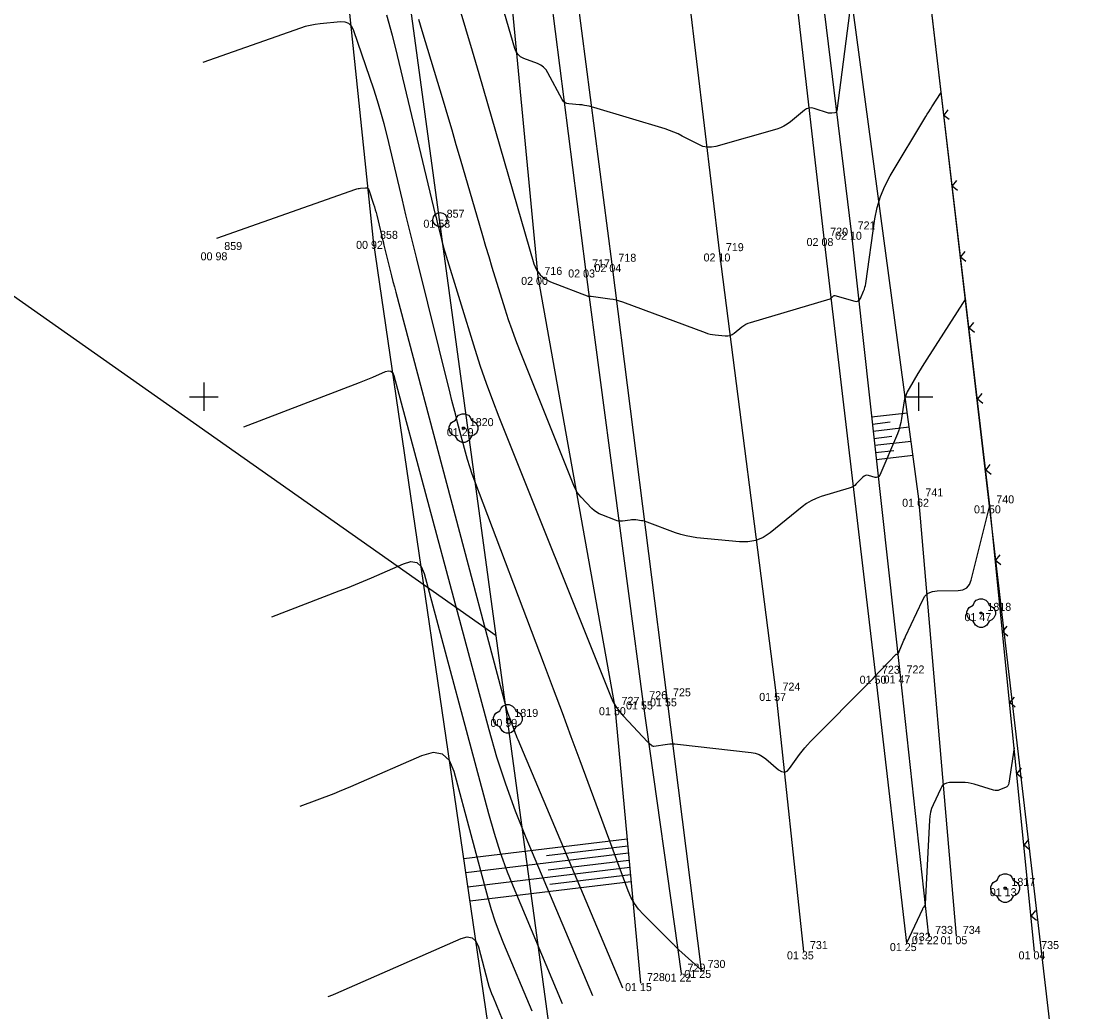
# Model space of a CAD drawing. Extents: x -711234 to -710007, y -1026313 to -1025448.
# Drawn here: x -710906.39 to -710869.22, y -1026121.51 to -1026086.87 of the extents above; entities that cross this region are included whole.
import ezdxf

# ---------------------------------------------------------------- set-up
doc = ezdxf.new("R2010")
doc.units = 0
for name, color, linetype in [('Ex_Major Contours', 7, 'Continuous'), ('Ex_Minor Contours', 7, 'Continuous'), ('Z_body', 7, 'Continuous'), ('Z_body_cisla', 7, 'Continuous'), ('Z_body_vysky_redukovane', 7, 'Continuous'), ('Z_hektometricka_sit', 7, 'Continuous'), ('Z_hrany_paty', 7, 'Continuous'), ('Z_katastr_hranice', 7, 'Continuous'), ('Z_komunikace', 7, 'Continuous'), ('Z_komunikace_osa', 7, 'Continuous'), ('Z_ploty', 7, 'Continuous'), ('Z_ploty_znacky', 7, 'Continuous'), ('Z_pole_rozhranni', 7, 'Continuous'), ('Z_technicke_srafy', 7, 'Continuous'), ('Z_vdz12_plna', 7, 'Continuous'), ('Z_zelen_jednotliva', 7, 'Continuous')]:
    doc.layers.add(name, color=color, linetype=linetype)

# ---------------------------------------------------------------- blocks, each defined once
blk = doc.blocks.new('POINT_DISPLAY')
blk.add_line((0, 0), (0, 0))
blk = doc.blocks.new('Z10001')
blk.add_circle((0, 0), 0.25)
blk = doc.blocks.new('Z24')
for p, q in [((-0.28, 0.28), (-0.23, 0.38)), ((-0.23, 0.38), (-0.17, 0.45)), ((-0.17, 0.45), (-0.05, 0.5)), ((-0.05, 0.5), (0.05, 0.5)), ((0.05, 0.5), (0.17, 0.45)), ((0.17, 0.45), (0.23, 0.38)), ((0.23, 0.38), (0.28, 0.28)), ((-0.5, 0.05), (-0.47, 0.13)), ((-0.5, -0.05), (-0.5, 0.05)), ((-0.47, 0.13), (-0.42, 0.2)), ((-0.42, 0.2), (-0.28, 0.28)), ((-0.03, -0.03), (-0.03, 0.03)), ((-0.03, 0.03), (0.03, 0.03)), ((0.03, 0.03), (0.03, -0.03)), ((0.28, 0.28), (0.42, 0.2)), ((0.42, 0.2), (0.47, 0.13)), ((0.47, 0.13), (0.5, 0.05)), ((0.5, 0.05), (0.5, -0.05)), ((-0.45, -0.17), (-0.5, -0.05)), ((-0.38, -0.23), (-0.45, -0.17)), ((-0.28, -0.28), (-0.38, -0.23)), ((-0.2, -0.42), (-0.28, -0.28)), ((0.03, -0.03), (-0.03, -0.03)), ((0.28, -0.28), (0.2, -0.42)), ((0.38, -0.23), (0.28, -0.28)), ((0.45, -0.17), (0.38, -0.23)), ((0.5, -0.05), (0.45, -0.17)), ((-0.13, -0.47), (-0.2, -0.42)), ((-0.05, -0.5), (-0.13, -0.47)), ((0.05, -0.5), (-0.05, -0.5)), ((0.13, -0.47), (0.05, -0.5)), ((0.2, -0.42), (0.13, -0.47))]:
    blk.add_line(p, q)
blk = doc.blocks.new('Z212')
for p, q in [((-0.17, 0.17), (0, 0)), ((0, 0), (0.17, 0.17))]:
    blk.add_line(p, q)

msp = doc.modelspace()

# ---------------------------------------------------------------- linework, layer by layer
at = {"layer": 'Ex_Major Contours'}
for points in [[(-710891.08, -1026086.336), (-710890.846, -1026087.122), (-710890.615, -1026087.909), (-710890.385, -1026088.696), (-710888.454, -1026095.349), (-710888.367, -1026095.561), (-710888.241, -1026095.737), (-710888.076, -1026095.877), (-710887.871, -1026095.981), (-710886.537, -1026096.49), (-710886.531, -1026096.492), (-710886.525, -1026096.493), (-710886.518, -1026096.493), (-710886.512, -1026096.493), (-710886.486, -1026096.489), (-710886.479, -1026096.489), (-710886.472, -1026096.488), (-710886.466, -1026096.489), (-710886.459, -1026096.489), (-710885.798, -1026096.572), (-710885.686, -1026096.589), (-710885.576, -1026096.613), (-710885.468, -1026096.643), (-710885.361, -1026096.679), (-710882.463, -1026097.757), (-710882.379, -1026097.785), (-710882.294, -1026097.808), (-710882.207, -1026097.825), (-710882.119, -1026097.837), (-710881.761, -1026097.873), (-710881.677, -1026097.873), (-710881.598, -1026097.858), (-710881.523, -1026097.827), (-710881.454, -1026097.78), (-710881.185, -1026097.561), (-710881.115, -1026097.51), (-710881.042, -1026097.467), (-710880.965, -1026097.431), (-710880.884, -1026097.402), (-710878.095, -1026096.572), (-710878.078, -1026096.566), (-710878.063, -1026096.558), (-710878.048, -1026096.548), (-710878.035, -1026096.535), (-710877.985, -1026096.483), (-710877.972, -1026096.472), (-710877.957, -1026096.466), (-710877.942, -1026096.464), (-710877.925, -1026096.466), (-710877.223, -1026096.657), (-710877.16, -1026096.665), (-710877.107, -1026096.652), (-710877.064, -1026096.618), (-710877.032, -1026096.564), (-710876.921, -1026096.305), (-710876.896, -1026096.24), (-710876.875, -1026096.173), (-710876.859, -1026096.106), (-710876.846, -1026096.037), (-710876.524, -1026093.774), (-710876.448, -1026093.381), (-710876.335, -1026093.001), (-710876.183, -1026092.634), (-710875.994, -1026092.281), (-710874.745, -1026090.204), (-710874.693, -1026090.119), (-710874.64, -1026090.033), (-710874.587, -1026089.948), (-710874.533, -1026089.864), (-710874.208, -1026089.358)], [(-710899.55, -1026094.458), (-710894.69, -1026092.747), (-710894.649, -1026092.734), (-710894.607, -1026092.723), (-710894.565, -1026092.715), (-710894.522, -1026092.71), (-710894.35, -1026092.694), (-710894.311, -1026092.695), (-710894.278, -1026092.708), (-710894.254, -1026092.732), (-710894.236, -1026092.768), (-710894.068, -1026093.265), (-710894.036, -1026093.361), (-710894.007, -1026093.459), (-710893.98, -1026093.557), (-710893.955, -1026093.656), (-710893.824, -1026094.204), (-710893.794, -1026094.328), (-710893.764, -1026094.453), (-710893.733, -1026094.577), (-710893.703, -1026094.701), (-710893.483, -1026095.588), (-710893.435, -1026095.777), (-710893.387, -1026095.966), (-710893.339, -1026096.155), (-710893.289, -1026096.343), (-710889.444, -1026110.845), (-710889.432, -1026110.888), (-710889.42, -1026110.93), (-710889.405, -1026110.972), (-710889.39, -1026111.014), (-710889.328, -1026111.179), (-710889.312, -1026111.221), (-710889.297, -1026111.262), (-710889.281, -1026111.303), (-710889.266, -1026111.345), (-710889.134, -1026111.701), (-710889.107, -1026111.774), (-710889.078, -1026111.847), (-710889.049, -1026111.919), (-710889.019, -1026111.991), (-710885.361, -1026120.674)], [(-710895.657, -1026120.978), (-710895.495, -1026120.915), (-710895.468, -1026120.905), (-710895.441, -1026120.894), (-710895.414, -1026120.883), (-710895.387, -1026120.871), (-710891.007, -1026118.953), (-710890.791, -1026118.893), (-710890.617, -1026118.922), (-710890.486, -1026119.039), (-710890.397, -1026119.246), (-710890.066, -1026120.484), (-710890.028, -1026120.617), (-710889.985, -1026120.748), (-710889.938, -1026120.877), (-710889.887, -1026121.005), (-710889.565, -1026121.769)]]:
    msp.add_lwpolyline(points, dxfattribs=at)
at = {"layer": 'Ex_Minor Contours'}
for points in [[(-710877.365, -1026086.208), (-710877.862, -1026090), (-710877.869, -1026090.025), (-710877.882, -1026090.044), (-710877.9, -1026090.058), (-710877.925, -1026090.066), (-710878.036, -1026090.085), (-710878.064, -1026090.088), (-710878.091, -1026090.088), (-710878.119, -1026090.084), (-710878.146, -1026090.078), (-710878.655, -1026089.917), (-710878.747, -1026089.898), (-710878.834, -1026089.903), (-710878.916, -1026089.931), (-710878.994, -1026089.983), (-710879.482, -1026090.386), (-710879.591, -1026090.468), (-710879.708, -1026090.537), (-710879.831, -1026090.594), (-710879.96, -1026090.638), (-710882.088, -1026091.247), (-710882.243, -1026091.276), (-710882.395, -1026091.276), (-710882.543, -1026091.245), (-710882.689, -1026091.185), (-710883.265, -1026090.882), (-710883.41, -1026090.809), (-710883.559, -1026090.744), (-710883.71, -1026090.686), (-710883.864, -1026090.636), (-710886.362, -1026089.88), (-710886.403, -1026089.868), (-710886.443, -1026089.858), (-710886.484, -1026089.848), (-710886.525, -1026089.84), (-710886.69, -1026089.81), (-710886.732, -1026089.803), (-710886.773, -1026089.797), (-710886.815, -1026089.792), (-710886.857, -1026089.789), (-710887.238, -1026089.759), (-710887.31, -1026089.745), (-710887.372, -1026089.716), (-710887.424, -1026089.671), (-710887.466, -1026089.61), (-710887.965, -1026088.671), (-710888.033, -1026088.566), (-710888.117, -1026088.477), (-710888.215, -1026088.405), (-710888.329, -1026088.351), (-710888.813, -1026088.166), (-710888.924, -1026088.111), (-710889.013, -1026088.035), (-710889.081, -1026087.94), (-710889.128, -1026087.826), (-710890.128, -1026084.381)], [(-710882.61, -1026120.05), (-710883.389, -1026119.345), (-710883.406, -1026119.33), (-710883.422, -1026119.314), (-710883.438, -1026119.298), (-710883.454, -1026119.281), (-710883.517, -1026119.215), (-710883.533, -1026119.198), (-710883.549, -1026119.182), (-710883.565, -1026119.165), (-710883.581, -1026119.149), (-710884.625, -1026118.11), (-710884.793, -1026117.924), (-710884.938, -1026117.723), (-710885.061, -1026117.508), (-710885.16, -1026117.278), (-710886.84, -1026112.734), (-710887.15, -1026111.898), (-710887.461, -1026111.062), (-710887.775, -1026110.227), (-710888.089, -1026109.393), (-710890.524, -1026102.955), (-710890.616, -1026102.705), (-710890.7, -1026102.452), (-710890.778, -1026102.197), (-710890.85, -1026101.94), (-710891.124, -1026100.908), (-710891.192, -1026100.65), (-710891.258, -1026100.391), (-710891.324, -1026100.133), (-710891.389, -1026099.874), (-710892.555, -1026095.174), (-710892.682, -1026094.662), (-710892.807, -1026094.149), (-710892.932, -1026093.636), (-710893.055, -1026093.123), (-710893.595, -1026090.861), (-710893.697, -1026090.453), (-710893.809, -1026090.049), (-710893.93, -1026089.647), (-710894.06, -1026089.248), (-710894.755, -1026087.199), (-710894.827, -1026087.053), (-710894.93, -1026086.953), (-710895.062, -1026086.9), (-710895.225, -1026086.893), (-710895.936, -1026086.959), (-710896.113, -1026086.981), (-710896.287, -1026087.014), (-710896.459, -1026087.057), (-710896.628, -1026087.111), (-710900.045, -1026088.315)], [(-710893.611, -1026086.639), (-710893.415, -1026087.35), (-710893.235, -1026088.066), (-710891.907, -1026093.627), (-710891.881, -1026093.737), (-710891.854, -1026093.846), (-710891.827, -1026093.956), (-710891.8, -1026094.065), (-710891.692, -1026094.503), (-710891.664, -1026094.612), (-710891.634, -1026094.72), (-710891.603, -1026094.829), (-710891.571, -1026094.937), (-710890.523, -1026098.332), (-710890.331, -1026098.931), (-710890.127, -1026099.527), (-710889.911, -1026100.118), (-710889.683, -1026100.705), (-710885.779, -1026110.463), (-710885.691, -1026110.656), (-710885.586, -1026110.838), (-710885.465, -1026111.01), (-710885.326, -1026111.171), (-710884.477, -1026112.069), (-710884.461, -1026112.086), (-710884.445, -1026112.102), (-710884.428, -1026112.118), (-710884.412, -1026112.133), (-710884.344, -1026112.194), (-710884.326, -1026112.207), (-710884.307, -1026112.216), (-710884.287, -1026112.22), (-710884.265, -1026112.219), (-710883.785, -1026112.156), (-710883.697, -1026112.147), (-710883.61, -1026112.144), (-710883.522, -1026112.146), (-710883.435, -1026112.153), (-710880.852, -1026112.447), (-710880.712, -1026112.473), (-710880.58, -1026112.519), (-710880.457, -1026112.584), (-710880.343, -1026112.669), (-710879.902, -1026113.047), (-710879.795, -1026113.115), (-710879.694, -1026113.13), (-710879.6, -1026113.092), (-710879.512, -1026113), (-710879.163, -1026112.515), (-710879.074, -1026112.396), (-710878.981, -1026112.282), (-710878.884, -1026112.171), (-710878.782, -1026112.064), (-710876.686, -1026109.947), (-710876.593, -1026109.853), (-710876.501, -1026109.759), (-710876.409, -1026109.664), (-710876.318, -1026109.569), (-710875.78, -1026109.007), (-710875.776, -1026109.003), (-710875.77, -1026109.001), (-710875.765, -1026109), (-710875.759, -1026109.001), (-710875.734, -1026109.008), (-710875.729, -1026109.008), (-710875.724, -1026109.007), (-710875.72, -1026109.004), (-710875.717, -1026108.999), (-710875.563, -1026108.638), (-710875.536, -1026108.576), (-710875.509, -1026108.514), (-710875.481, -1026108.453), (-710875.453, -1026108.391), (-710874.866, -1026107.124), (-710874.776, -1026106.978), (-710874.659, -1026106.873), (-710874.516, -1026106.809), (-710874.346, -1026106.786), (-710873.613, -1026106.775), (-710873.447, -1026106.751), (-710873.315, -1026106.682), (-710873.219, -1026106.57), (-710873.157, -1026106.414), (-710872.5, -1026103.8)], [(-710873.354, -1026096.579), (-710874.712, -1026098.692), (-710874.791, -1026098.816), (-710874.869, -1026098.94), (-710874.946, -1026099.065), (-710875.022, -1026099.19), (-710875.333, -1026099.708), (-710875.398, -1026099.829), (-710875.45, -1026099.954), (-710875.489, -1026100.084), (-710875.515, -1026100.219), (-710875.593, -1026100.767), (-710875.617, -1026100.902), (-710875.649, -1026101.036), (-710875.69, -1026101.166), (-710875.74, -1026101.295), (-710876.358, -1026102.742), (-710876.385, -1026102.788), (-710876.422, -1026102.817), (-710876.466, -1026102.828), (-710876.52, -1026102.821), (-710876.75, -1026102.758), (-710876.806, -1026102.75), (-710876.857, -1026102.756), (-710876.905, -1026102.778), (-710876.948, -1026102.813), (-710877.177, -1026103.052), (-710877.231, -1026103.103), (-710877.29, -1026103.144), (-710877.355, -1026103.178), (-710877.424, -1026103.204), (-710878.401, -1026103.495), (-710878.584, -1026103.559), (-710878.757, -1026103.64), (-710878.922, -1026103.737), (-710879.077, -1026103.852), (-710880.188, -1026104.756), (-710880.432, -1026104.92), (-710880.692, -1026105.029), (-710880.97, -1026105.082), (-710881.263, -1026105.079), (-710882.751, -1026104.931), (-710882.943, -1026104.905), (-710883.132, -1026104.868), (-710883.318, -1026104.818), (-710883.501, -1026104.756), (-710884.499, -1026104.385), (-710884.547, -1026104.369), (-710884.595, -1026104.356), (-710884.644, -1026104.345), (-710884.694, -1026104.338), (-710884.893, -1026104.312), (-710884.943, -1026104.308), (-710884.993, -1026104.306), (-710885.043, -1026104.308), (-710885.093, -1026104.313), (-710885.361, -1026104.348), (-710885.422, -1026104.352), (-710885.482, -1026104.349), (-710885.541, -1026104.338), (-710885.599, -1026104.32), (-710886.082, -1026104.136), (-710886.178, -1026104.093), (-710886.268, -1026104.04), (-710886.351, -1026103.978), (-710886.428, -1026103.905), (-710886.798, -1026103.516), (-710886.879, -1026103.422), (-710886.95, -1026103.322), (-710887.011, -1026103.216), (-710887.063, -1026103.103), (-710888.951, -1026098.384), (-710889.09, -1026098.027), (-710889.221, -1026097.667), (-710889.345, -1026097.306), (-710889.461, -1026096.941), (-710889.913, -1026095.478), (-710890.025, -1026095.112), (-710890.136, -1026094.745), (-710890.245, -1026094.378), (-710890.353, -1026094.011), (-710891.025, -1026091.696), (-710891.173, -1026091.187), (-710891.322, -1026090.68), (-710891.473, -1026090.172), (-710891.625, -1026089.665), (-710892.366, -1026087.198), (-710892.482, -1026086.804)], [(-710898.606, -1026101.059), (-710894.554, -1026099.507), (-710894.439, -1026099.462), (-710894.324, -1026099.415), (-710894.21, -1026099.368), (-710894.096, -1026099.319), (-710893.643, -1026099.12), (-710893.54, -1026099.091), (-710893.457, -1026099.105), (-710893.394, -1026099.161), (-710893.352, -1026099.26), (-710890.039, -1026111.635), (-710889.764, -1026112.596), (-710889.456, -1026113.546), (-710889.116, -1026114.485), (-710888.744, -1026115.413), (-710886.412, -1026120.948)], [(-710897.623, -1026107.698), (-710895.267, -1026106.796), (-710894.982, -1026106.685), (-710894.698, -1026106.57), (-710894.416, -1026106.453), (-710894.135, -1026106.331), (-710893.015, -1026105.841), (-710892.76, -1026105.77), (-710892.555, -1026105.804), (-710892.401, -1026105.943), (-710892.296, -1026106.186), (-710890.048, -1026114.584), (-710889.852, -1026115.269), (-710889.633, -1026115.947), (-710889.39, -1026116.616), (-710889.125, -1026117.277), (-710887.463, -1026121.221)], [(-710888.514, -1026121.495), (-710889.506, -1026119.141), (-710889.664, -1026118.747), (-710889.809, -1026118.347), (-710889.94, -1026117.943), (-710890.057, -1026117.534), (-710891.241, -1026113.112), (-710891.407, -1026112.724), (-710891.653, -1026112.503), (-710891.98, -1026112.449), (-710892.387, -1026112.561), (-710894.683, -1026113.567), (-710894.876, -1026113.65), (-710895.07, -1026113.731), (-710895.265, -1026113.81), (-710895.461, -1026113.886), (-710896.64, -1026114.338)], [(-710871.652, -1026112.278), (-710871.837, -1026113.512), (-710871.85, -1026113.563), (-710871.875, -1026113.606), (-710871.91, -1026113.64), (-710871.957, -1026113.666), (-710872.163, -1026113.752), (-710872.215, -1026113.768), (-710872.267, -1026113.776), (-710872.32, -1026113.774), (-710872.373, -1026113.762), (-710873.052, -1026113.553), (-710873.157, -1026113.525), (-710873.263, -1026113.506), (-710873.37, -1026113.495), (-710873.479, -1026113.492), (-710873.915, -1026113.498), (-710874.016, -1026113.512), (-710874.102, -1026113.55), (-710874.171, -1026113.613), (-710874.225, -1026113.7), (-710874.489, -1026114.271), (-710874.542, -1026114.401), (-710874.582, -1026114.534), (-710874.609, -1026114.67), (-710874.622, -1026114.809), (-710874.767, -1026117.74), (-710874.769, -1026117.757), (-710874.773, -1026117.774), (-710874.78, -1026117.79), (-710874.789, -1026117.805), (-710874.828, -1026117.864), (-710874.838, -1026117.879), (-710874.847, -1026117.895), (-710874.856, -1026117.91), (-710874.863, -1026117.926), (-710875.42, -1026119.11)]]:
    msp.add_lwpolyline(points, dxfattribs=at)
at = {"layer": 'Z_hektometricka_sit'}
for p, q in [((-710900, -1026099.5), (-710900, -1026100.5)), ((-710875, -1026099.5), (-710875, -1026100.5)), ((-710900.5, -1026100), (-710899.5, -1026100)), ((-710875.5, -1026100), (-710874.5, -1026100))]:
    msp.add_line(p, q, dxfattribs=at)
at = {"layer": 'Z_hrany_paty'}
for p, q in [((-710889.85, -1026079.72), (-710888.32, -1026095.81)), ((-710874.99, -1026103.57), (-710877.27, -1026086.56)), ((-710888.32, -1026095.81), (-710885.62, -1026110.86)), ((-710873.67, -1026118.87), (-710874.99, -1026103.57)), ((-710885.62, -1026110.86), (-710884.73, -1026120.51))]:
    msp.add_line(p, q, dxfattribs=at)
at = {"layer": 'Z_katastr_hranice'}
msp.add_line((-710885.22, -1026141.88), (-710889.78, -1026108.36), dxfattribs=at)
for points in [[(-710889.78, -1026108.36), (-711036.33, -1026005.25), (-711182.89, -1025902.14)], [(-710869.22, -1026132.07), (-710876.56, -1026069.18), (-710887.07, -1025978.66), (-710888.56, -1025976.86)], [(-710889.78, -1026108.36), (-710894.44, -1026074.09), (-710896.69, -1026055.45)]]:
    msp.add_lwpolyline(points, dxfattribs=at)
at = {"layer": 'Z_komunikace'}
for p, q in [((-710879.33, -1026078.09), (-710877.36, -1026094.23)), ((-710888.71, -1026079.46), (-710886.65, -1026095.55)), ((-710877.36, -1026094.23), (-710875.64, -1026109.75)), ((-710886.65, -1026095.55), (-710884.65, -1026110.66)), ((-710875.64, -1026109.75), (-710874.65, -1026118.87)), ((-710884.65, -1026110.66), (-710883.3, -1026120.18))]:
    msp.add_line(p, q, dxfattribs=at)
at = {"layer": 'Z_komunikace_osa'}
for p, q in [((-710883.93, -1026078.67), (-710881.96, -1026094.99)), ((-710881.96, -1026094.99), (-710879.99, -1026110.36)), ((-710879.99, -1026110.36), (-710879.02, -1026119.4))]:
    msp.add_line(p, q, dxfattribs=at)
at = {"layer": 'Z_ploty'}
for p, q in [((-710872.5, -1026103.8), (-710874.55, -1026086.47)), ((-710870.94, -1026119.4), (-710872.5, -1026103.8))]:
    msp.add_line(p, q, dxfattribs=at)
at = {"layer": 'Z_pole_rozhranni'}
for p, q in [((-710894.07, -1026094.55), (-710896.88, -1026067.52)), ((-710890.07, -1026121.9), (-710894.07, -1026094.55))]:
    msp.add_line(p, q, dxfattribs=at)
at = {"layer": 'Z_technicke_srafy'}
for p, q in [((-710876.64, -1026100.71), (-710875.39, -1026100.56)), ((-710876.61, -1026100.96), (-710875.99, -1026100.88)), ((-710876.59, -1026101.21), (-710875.33, -1026101.05)), ((-710876.56, -1026101.46), (-710875.93, -1026101.38)), ((-710876.53, -1026101.7), (-710875.26, -1026101.55)), ((-710876.5, -1026101.95), (-710875.87, -1026101.88)), ((-710876.48, -1026102.2), (-710875.19, -1026102.04)), ((-710885.19, -1026115.48), (-710890.91, -1026116.16)), ((-710885.15, -1026115.97), (-710890.84, -1026116.65)), ((-710885.17, -1026115.72), (-710888.02, -1026116.06)), ((-710885.13, -1026116.22), (-710887.96, -1026116.56)), ((-710885.1, -1026116.47), (-710890.77, -1026117.15)), ((-710885.06, -1026116.97), (-710890.69, -1026117.64)), ((-710885.08, -1026116.72), (-710887.9, -1026117.06))]:
    msp.add_line(p, q, dxfattribs=at)
at = {"layer": 'Z_vdz12_plna'}
for p, q in [((-710880.19, -1026078.24), (-710878.31, -1026094.45)), ((-710887.8, -1026079.37), (-710885.73, -1026095.36)), ((-710878.31, -1026094.45), (-710876.5, -1026109.76)), ((-710885.73, -1026095.36), (-710883.81, -1026110.55)), ((-710876.5, -1026109.76), (-710875.42, -1026119.11)), ((-710883.81, -1026110.55), (-710882.61, -1026120.05))]:
    msp.add_line(p, q, dxfattribs=at)

# ---------------------------------------------------------------- block references
at = {"layer": 'Z_body'}
for p in [(-710891.74, -1026093.81), (-710877.36, -1026094.23), (-710894.07, -1026094.55), (-710878.31, -1026094.45), (-710899.51, -1026094.95), (-710881.96, -1026094.99), (-710885.73, -1026095.36), (-710888.32, -1026095.81), (-710886.65, -1026095.55), (-710890.92, -1026101.1), (-710874.99, -1026103.57), (-710872.5, -1026103.8), (-710872.81, -1026107.57), (-710876.5, -1026109.76), (-710875.64, -1026109.75), (-710879.99, -1026110.36), (-710884.65, -1026110.66), (-710883.81, -1026110.55), (-710885.62, -1026110.86), (-710889.37, -1026111.27), (-710871.97, -1026117.19), (-710874.65, -1026118.87), (-710873.67, -1026118.87), (-710875.42, -1026119.11), (-710879.02, -1026119.4), (-710870.94, -1026119.4), (-710882.61, -1026120.05), (-710883.3, -1026120.18), (-710884.73, -1026120.51)]:
    msp.add_blockref('POINT_DISPLAY', p, dxfattribs=at)
at = {"layer": 'Z_ploty_znacky'}
for p, rotation in [((-710874.12, -1026090.15), -83.30000000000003), ((-710873.82, -1026092.63), -83.30000000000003), ((-710873.53, -1026095.11), -83.30000000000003), ((-710873.23, -1026097.59), -83.30000000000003), ((-710872.94, -1026100.08), -83.30000000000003), ((-710872.65, -1026102.56), -83.30000000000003), ((-710872.31, -1026105.72), -84.30000000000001), ((-710872.06, -1026108.21), -84.30000000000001), ((-710871.81, -1026110.69), -84.30000000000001), ((-710871.56, -1026113.18), -84.30000000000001), ((-710871.31, -1026115.67), -84.30000000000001), ((-710871.06, -1026118.16), -84.30000000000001)]:
    msp.add_blockref('Z212', p, dxfattribs=dict(at, rotation=rotation))
at = {"layer": 'Z_zelen_jednotliva'}
for name, p in [('Z10001', (-710891.74, -1026093.81)), ('Z24', (-710890.92, -1026101.1)), ('Z24', (-710872.81, -1026107.57)), ('Z24', (-710889.37, -1026111.27)), ('Z24', (-710871.97, -1026117.19))]:
    msp.add_blockref(name, p, dxfattribs=at)

# ---------------------------------------------------------------- texts
at = {"layer": 'Z_body_cisla'}
for s, p in [('857', (-710891.51, -1026093.74)), ('721', (-710877.13, -1026094.15)), ('858', (-710893.84, -1026094.48)), ('720', (-710878.09, -1026094.37)), ('859', (-710899.29, -1026094.87)), ('719', (-710881.74, -1026094.91)), ('718', (-710885.5, -1026095.28)), ('716', (-710888.09, -1026095.74)), ('717', (-710886.42, -1026095.48)), ('1820', (-710890.7, -1026101.03)), ('741', (-710874.76, -1026103.49)), ('740', (-710872.28, -1026103.73)), ('1818', (-710872.59, -1026107.49)), ('723', (-710876.28, -1026109.69)), ('722', (-710875.42, -1026109.68)), ('724', (-710879.76, -1026110.28)), ('726', (-710884.42, -1026110.58)), ('725', (-710883.59, -1026110.48)), ('727', (-710885.39, -1026110.78)), ('1819', (-710889.14, -1026111.2)), ('1817', (-710871.75, -1026117.11)), ('733', (-710874.42, -1026118.79)), ('734', (-710873.45, -1026118.79)), ('732', (-710875.2, -1026119.03)), ('731', (-710878.8, -1026119.32)), ('735', (-710870.71, -1026119.32)), ('729', (-710883.08, -1026120.11)), ('730', (-710882.38, -1026119.98)), ('728', (-710884.5, -1026120.44))]:
    msp.add_text(s, height=0.28, dxfattribs=at).set_placement(p)
at = {"layer": 'Z_body_vysky_redukovane'}
for s, p in [('01 53', (-710892.323, -1026094.09)), ('02 10', (-710877.92, -1026094.51)), ('00 92', (-710894.677, -1026094.83)), ('02 08', (-710878.917, -1026094.73)), ('00 98', (-710900.117, -1026095.23)), ('02 10', (-710882.52, -1026095.27)), ('02 04', (-710886.337, -1026095.64)), ('02 00', (-710888.903, -1026096.09)), ('02 03', (-710887.257, -1026095.83)), ('01 29', (-710891.503, -1026101.38)), ('01 62', (-710875.573, -1026103.85)), ('01 50', (-710873.06, -1026104.08)), ('01 47', (-710873.393, -1026107.85)), ('01 50', (-710877.06, -1026110.04)), ('01 47', (-710876.223, -1026110.03)), ('01 57', (-710880.573, -1026110.64)), ('01 55', (-710885.233, -1026110.94)), ('01 55', (-710884.393, -1026110.83)), ('01 50', (-710886.18, -1026111.14)), ('00 99', (-710889.977, -1026111.55)), ('01 13', (-710872.507, -1026117.47)), ('01 22', (-710875.233, -1026119.15)), ('01 05', (-710874.23, -1026119.15)), ('01 25', (-710876.003, -1026119.39)), ('01 35', (-710879.603, -1026119.68)), ('01 04', (-710871.5, -1026119.68)), ('01 25', (-710883.193, -1026120.33)), ('01 22', (-710883.883, -1026120.46)), ('01 15', (-710885.267, -1026120.79))]:
    msp.add_text(s, height=0.28, dxfattribs=at).set_placement(p)

doc.saveas('drawing.dxf')
